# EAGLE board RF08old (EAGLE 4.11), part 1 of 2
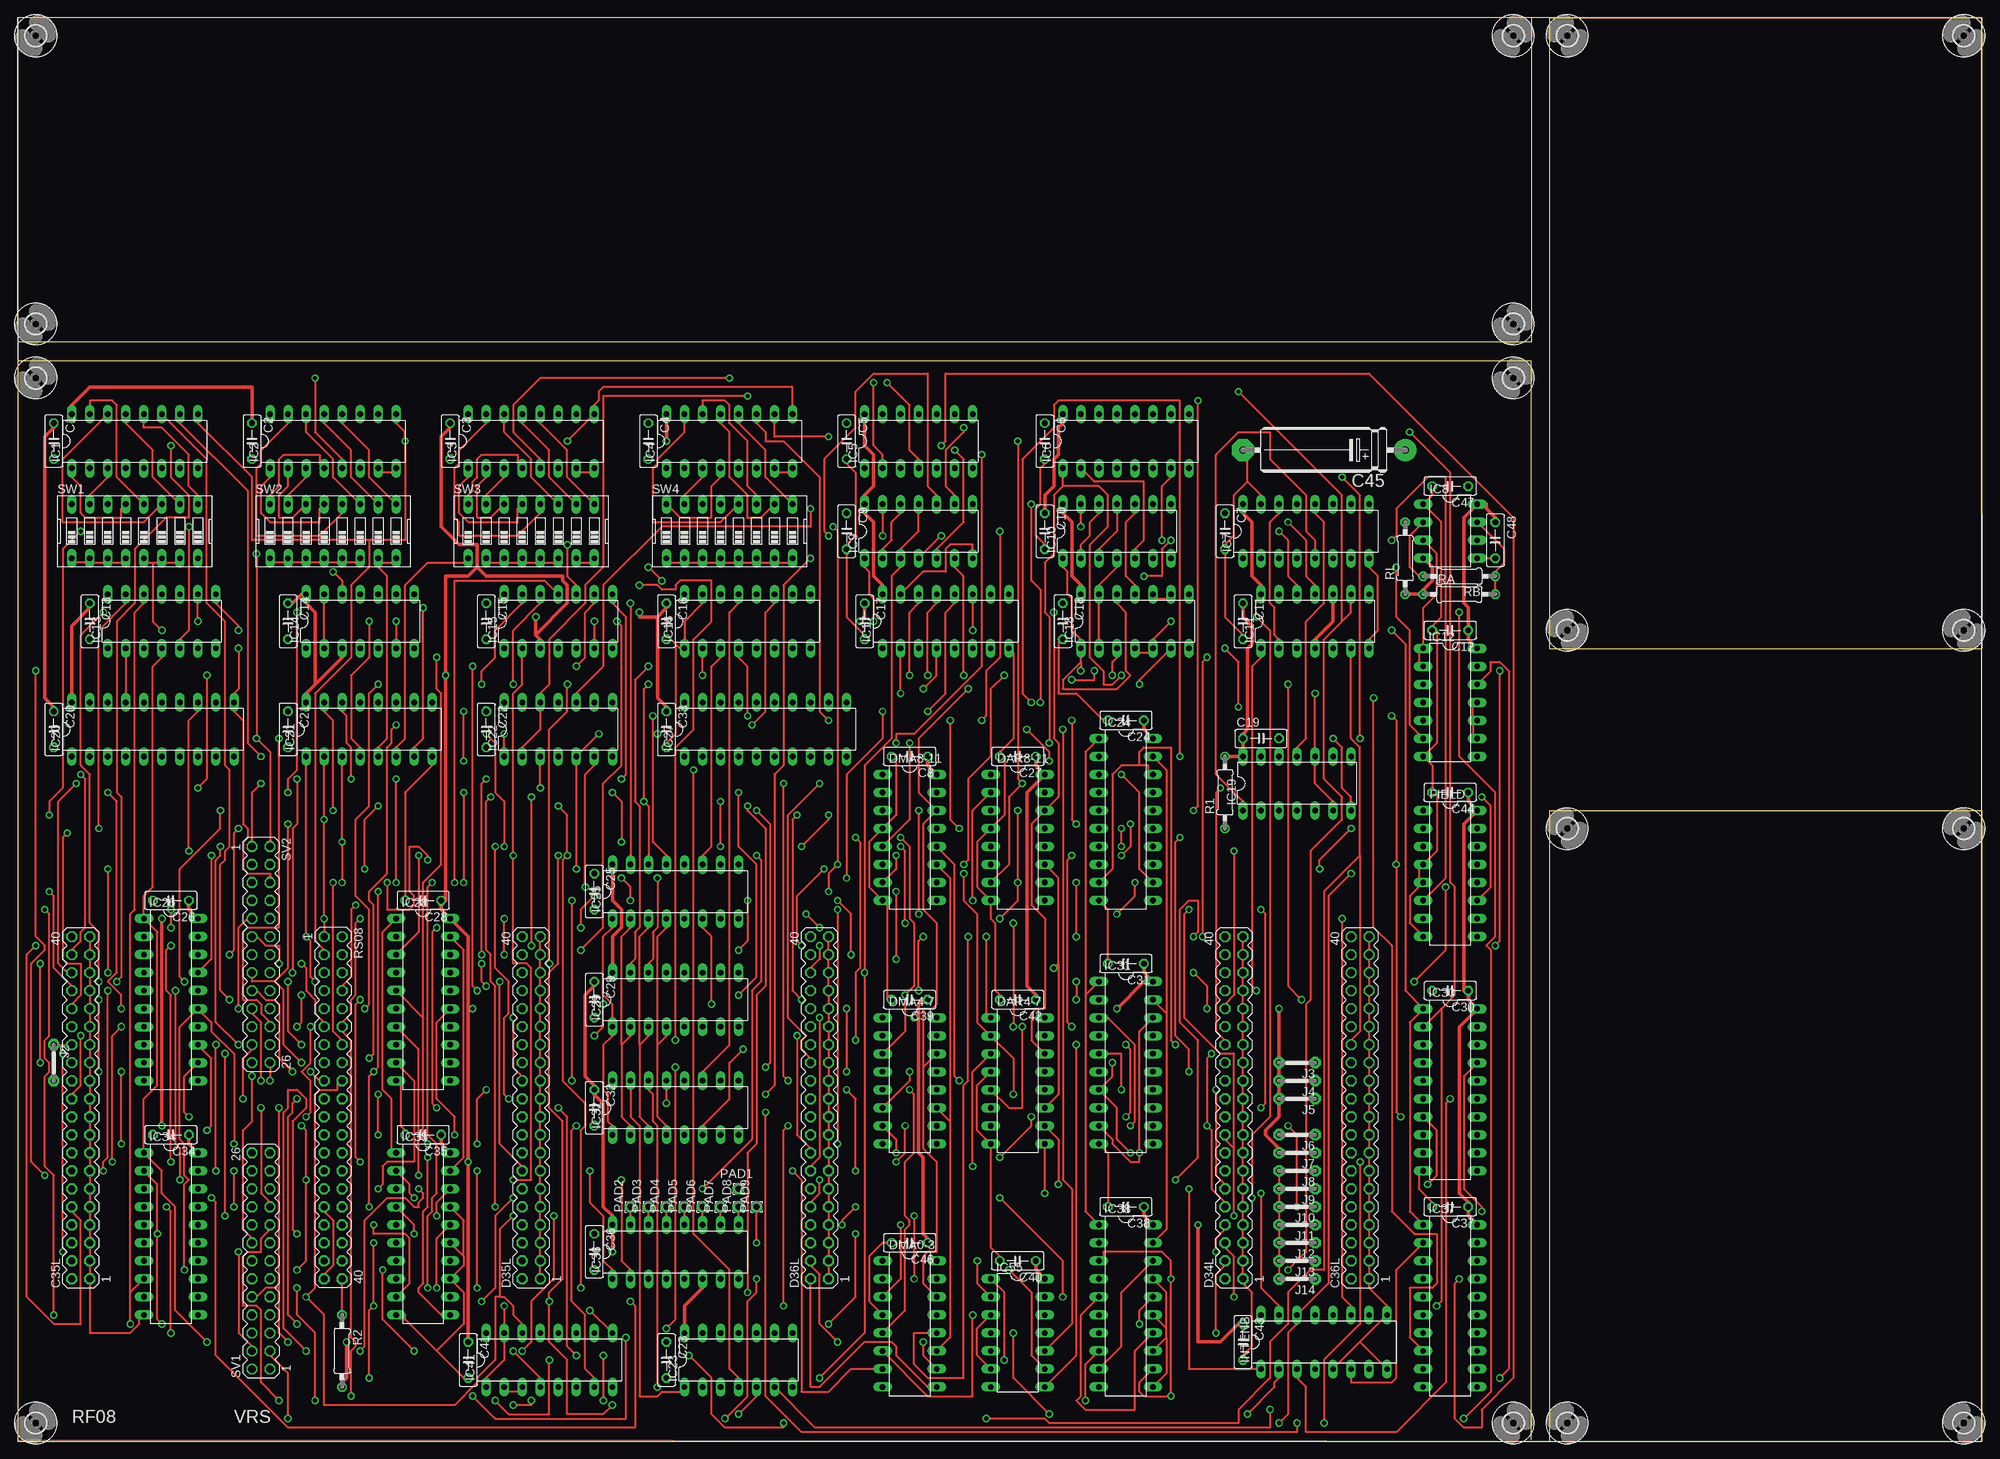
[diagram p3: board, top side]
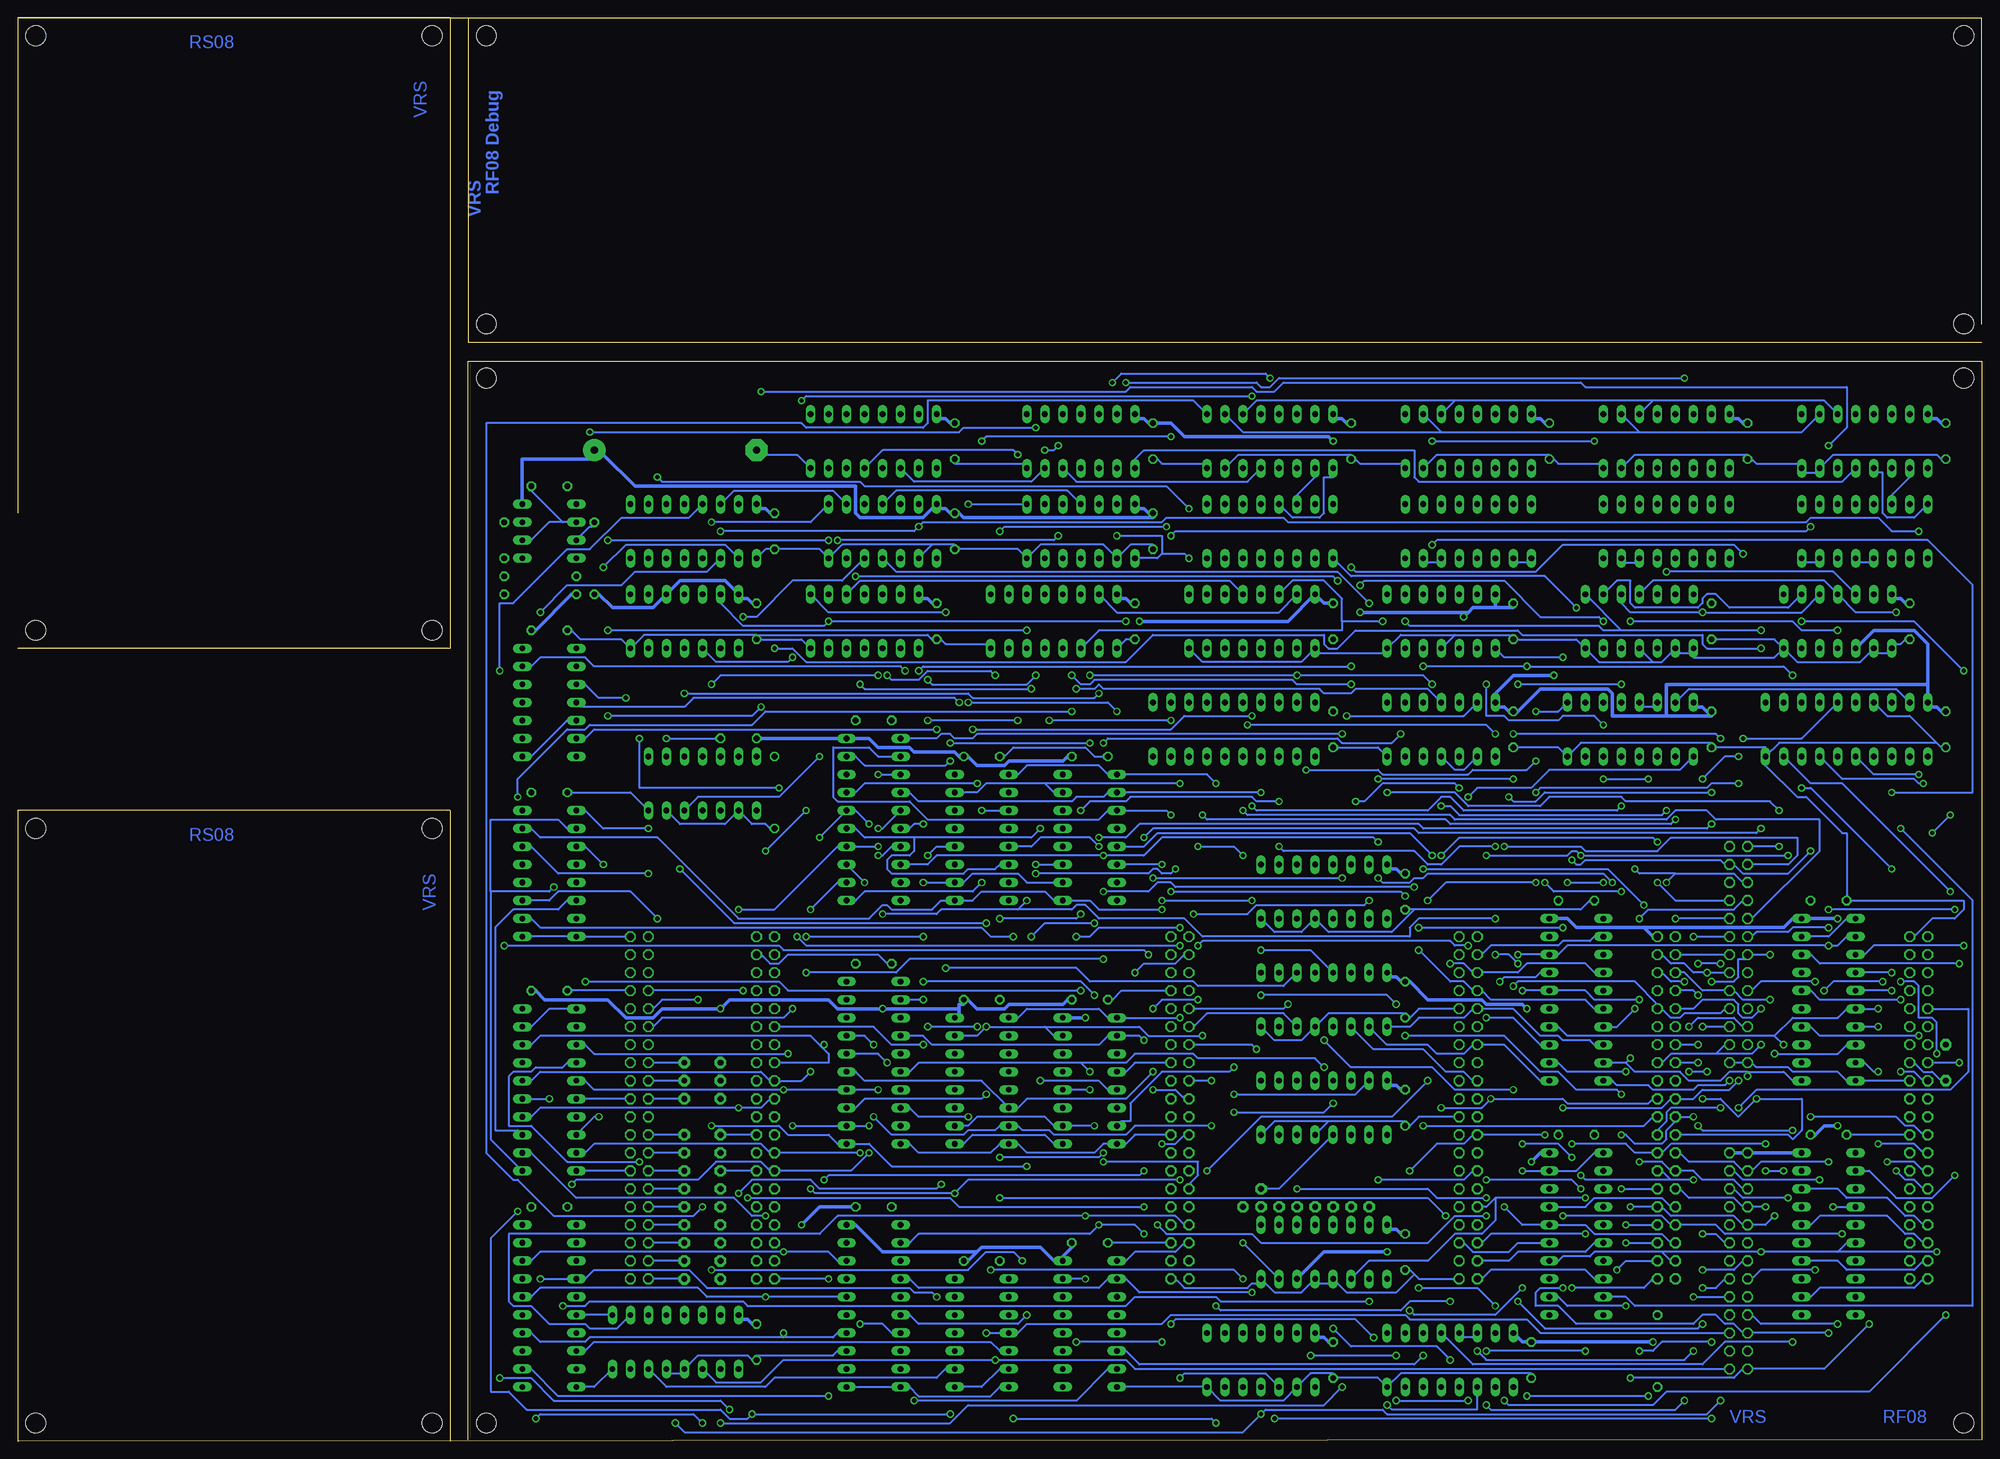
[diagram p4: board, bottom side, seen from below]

Size 276.86 x 200.67 mm. Coordinates in mm from the lower left corner, seen from the top.
Outline: 276.69,0 0.01,0.18 0.01,152.25 213.34,152.25 213.34,0.18
Outline: 215.9,0.01 215.9,88.92 276.86,88.92 276.86,0.01
Outline: 276.86,111.78 215.9,111.78 215.9,200.67 276.86,200.67
Outline: 276.86,200.67 0,200.67 0,157.49
Outline: 276.86,200.67 276.86,130.82
Outline: 0,154.95 213.36,154.95 213.36,200.67
Copper layers (1*16): Top 0.035mm / dielectric 1.5mm / Bottom 0.035mm
Design rules "olimex10mil": minimum track width 10mil, minimum drill 24mil, track to track 10mil, track to pad 10mil, pad to pad 10mil, via to via 10mil, smd to smd 10mil, copper to edge 40mil, drill to drill 10mil, minimum pad ring 10mil, minimum via ring 8mil, stop-mask expansion 0mil, vias tented up to drill 0mil, thermal gap 10mil
Net classes: 1 Power: width 0.508 mm

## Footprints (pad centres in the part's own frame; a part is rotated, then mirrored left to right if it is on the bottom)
C050-025X075 = drill 0.813 octagon: 1 -2.54,0; 2 2.54,0
MA20-2 = drill 1.016 octagon: 1 -24.13,-1.27; 2 -24.13,1.27; 3 -21.59,-1.27; 4 -21.59,1.27; 5 -19.05,-1.27; 6 -19.05,1.27; 7 -16.51,-1.27; 8 -16.51,1.27; 9 -13.97,-1.27; 10 -13.97,1.27; 11 -11.43,-1.27; 12 -11.43,1.27; 13 -8.89,-1.27; 14 -8.89,1.27; 15 -6.35,-1.27; 16 -6.35,1.27; 17 -3.81,-1.27; 18 -3.81,1.27; 19 -1.27,-1.27; 20 -1.27,1.27; 21 1.27,-1.27; 22 1.27,1.27; 23 3.81,-1.27; 24 3.81,1.27; 25 6.35,-1.27; 26 6.35,1.27; 27 8.89,-1.27; 28 8.89,1.27; 29 11.43,-1.27; 30 11.43,1.27; 31 13.97,-1.27; 32 13.97,1.27; 33 16.51,-1.27; 34 16.51,1.27; 35 19.05,-1.27; 36 19.05,1.27; 37 21.59,-1.27; 38 21.59,1.27; 39 24.13,-1.27; 40 24.13,1.27
E22-6 = drill 1.016 pad 3.15 round: + -11.43,0 | drill 1.016 pad 3.15 octagon: - 11.43,0
DIL16 = drill 0.813 long: 1 -8.89,-3.81; 2 -6.35,-3.81; 3 -3.81,-3.81; 4 -1.27,-3.81; 5 1.27,-3.81; 6 3.81,-3.81; 7 6.35,-3.81; 8 8.89,-3.81; 9 8.89,3.81; 10 6.35,3.81; 11 3.81,3.81; 12 1.27,3.81; 13 -1.27,3.81; 14 -3.81,3.81; 15 -6.35,3.81; 16 -8.89,3.81
DIL14 = drill 0.813 long: 1 -7.62,-3.81; 2 -5.08,-3.81; 3 -2.54,-3.81; 4 0,-3.81; 5 2.54,-3.81; 6 5.08,-3.81; 7 7.62,-3.81; 8 7.62,3.81; 9 5.08,3.81; 10 2.54,3.81; 11 0,3.81; 12 -2.54,3.81; 13 -5.08,3.81; 14 -7.62,3.81
DIL08 = drill 0.813 long: 1 -3.81,-3.81; 2 -1.27,-3.81; 3 1.27,-3.81; 4 3.81,-3.81; 5 3.81,3.81; 6 1.27,3.81; 7 -1.27,3.81; 8 -3.81,3.81
DIL20 = drill 0.813 long: 1 -11.43,-3.81; 2 -8.89,-3.81; 3 -6.35,-3.81; 4 -3.81,-3.81; 5 -1.27,-3.81; 6 1.27,-3.81; 7 3.81,-3.81; 8 6.35,-3.81; 9 8.89,-3.81; 10 11.43,-3.81; 11 11.43,3.81; 12 8.89,3.81; 13 6.35,3.81; 14 3.81,3.81; 15 1.27,3.81; 16 -1.27,3.81; 17 -3.81,3.81; 18 -6.35,3.81; 19 -8.89,3.81; 20 -11.43,3.81
05 = drill 0.813 pad 1.6 octagon: 1 -2.54,0; 2 2.54,0
1,6/0,8 = drill 0.813 pad 1.6 octagon: 1 0,0
0207/10 = drill 0.813 octagon: 1 -5.08,0; 2 5.08,0
MA13-2 = drill 1.016 octagon: 1 -15.24,-1.27; 2 -15.24,1.27; 3 -12.7,-1.27; 4 -12.7,1.27; 5 -10.16,-1.27; 6 -10.16,1.27; 7 -7.62,-1.27; 8 -7.62,1.27; 9 -5.08,-1.27; 10 -5.08,1.27; 11 -2.54,-1.27; 12 -2.54,1.27; 13 0,-1.27; 14 0,1.27; 15 2.54,-1.27; 16 2.54,1.27; 17 5.08,-1.27; 18 5.08,1.27; 19 7.62,-1.27; 20 7.62,1.27; 21 10.16,-1.27; 22 10.16,1.27; 23 12.7,-1.27; 24 12.7,1.27; 25 15.24,-1.27; 26 15.24,1.27
EDG-08 = drill 0.813 long: 1 -8.89,-3.81; 2 -6.35,-3.81; 3 -3.81,-3.81; 4 -1.27,-3.81; 5 1.27,-3.81; 6 3.81,-3.81; 7 6.35,-3.81; 8 8.89,-3.81; 9 8.89,3.81; 10 6.35,3.81; 11 3.81,3.81; 12 1.27,3.81; 13 -1.27,3.81; 14 -3.81,3.81; 15 -6.35,3.81; 16 -8.89,3.81
2,8 = hole 2.8: 0,0

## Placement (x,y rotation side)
C1  0.1  [C050-025X075]  5.08,140.98 270 top
C2  0.1  [C050-025X075]  33.02,140.98 270 top
C3  0.1  [C050-025X075]  60.96,140.98 270 top
C4  0.1  [C050-025X075]  88.9,140.98 270 top
C5  0.1  [C050-025X075]  116.84,140.98 270 top
C6  0.1  [C050-025X075]  144.78,140.98 270 top
C7  0.1  [C050-025X075]  170.18,128.28 270 top
C8  0.1  [C050-025X075]  125.73,96.53 180 top
C9  0.1  [C050-025X075]  116.84,128.28 270 top
C10  0.1  [C050-025X075]  144.78,128.28 270 top
C11  0.1  [C050-025X075]  172.72,115.58 270 top
C12  0.1  [C050-025X075]  201.93,114.31 180 top
C13  0.1  [C050-025X075]  10.16,115.58 270 top
C14  0.1  [C050-025X075]  38.1,115.58 270 top
C15  0.1  [C050-025X075]  66.04,115.58 270 top
C16  0.1  [C050-025X075]  91.44,115.58 270 top
C17  0.1  [C050-025X075]  119.38,115.58 270 top
C18  0.1  [C050-025X075]  147.32,115.58 270 top
C19  0.1  [C050-025X075]  175.26,99.08 0 top
C20  0.1  [C050-025X075]  5.08,100.34 270 top
C21  0.1  [C050-025X075]  38.1,100.34 270 top
C22  0.1  [C050-025X075]  66.04,100.34 270 top
C23  0.1  [C050-025X075]  91.44,11.45 270 top
C24  0.1  [C050-025X075]  156.21,101.61 180 top
C25  0.1  [C050-025X075]  81.28,77.48 270 top
C26  0.1  [C050-025X075]  21.59,76.22 180 top
C27  0.1  [C050-025X075]  140.97,96.53 180 top
C28  0.1  [C050-025X075]  57.15,76.22 180 top
C29  0.1  [C050-025X075]  81.28,62.24 270 top
C30  0.1  [C050-025X075]  201.93,63.52 180 top
C31  0.1  [C050-025X075]  156.21,67.33 180 top
C32  0.1  [C050-025X075]  81.28,47.01 270 top
C33  0.1  [C050-025X075]  91.44,100.34 270 top
C34  0.1  [C050-025X075]  21.59,43.2 180 top
C35  0.1  [C050-025X075]  57.15,43.2 180 top
C35L  [MA20-2]  8.89,47.01 90 top
C36  0.1  [C050-025X075]  81.28,26.69 270 top
C36L  [MA20-2]  189.23,47.01 90 top
C37  0.1  [C050-025X075]  201.93,33.04 180 top
C38  0.1  [C050-025X075]  156.21,33.04 180 top
C39  0.1  [C050-025X075]  125.73,62.24 180 top
C40  0.1  [C050-025X075]  140.97,25.41 180 top
C41  0.1  [C050-025X075]  63.5,11.45 270 top
C42  0.1  [C050-025X075]  140.97,62.24 180 top
C43  0.1  [C050-025X075]  172.72,13.99 270 top
C44  0.1  [C050-025X075]  201.93,91.45 180 top
C45  100uf  [E22-6]  184.15,139.71 180 top
C46  0.1  [C050-025X075]  125.73,27.96 180 top
C47  0.1  [C050-025X075]  201.93,134.63 180 top
C48  0.1  [C050-025X075]  208.28,127.02 270 top
D34L  [MA20-2]  171.45,47.01 90 top
D35L  [MA20-2]  72.39,47.01 90 top
D36L  [MA20-2]  113.03,47.01 90 top
DAR4-7  74LS193N  [DIL16]  140.97,50.81 270 top
DAR8-11  74LS193N  [DIL16]  140.97,85.11 270 top
DMA0-3  74LS193N  [DIL16]  125.73,16.53 270 top
DMA4-7  74LS193N  [DIL16]  125.73,50.81 270 top
DMA8-11  74LS193N  [DIL16]  125.73,85.11 270 top
FIELD  74LS193N  [DIL16]  201.93,80.03 270 top
IC1  74LS151N  [DIL16]  16.51,140.98 0 top
IC2  74LS151N  [DIL16]  44.45,140.98 0 top
IC3  74LS151N  [DIL16]  72.39,140.98 0 top
IC4  74LS151N  [DIL16]  100.33,140.98 0 top
IC5  74LS20N  [DIL14]  127,140.98 0 top
IC6  74LS139N  [DIL16]  156.21,140.98 0 top
IC7  74LS139N  [DIL16]  181.61,128.28 0 top
IC8  LM555N  [DIL08]  201.93,128.28 270 top
IC9  74S74N  [DIL14]  127,128.28 0 top
IC10  74S74N  [DIL14]  154.94,128.28 0 top
IC11  74S74N  [DIL14]  182.88,115.58 0 top
IC12  74LS00N  [DIL14]  201.93,104.16 270 top
IC13  74180N  [DIL14]  20.32,115.58 0 top
IC14  74180N  [DIL14]  48.26,115.58 0 top
IC15  74180N  [DIL14]  76.2,115.58 0 top
IC16  74LS139N  [DIL16]  102.87,115.58 0 top
IC17  74LS139N  [DIL16]  130.81,115.58 0 top
IC18  74LS00N  [DIL14]  157.48,115.58 0 top
IC19  7407N  [DIL14]  180.34,92.72 0 top
IC20  74S240N  [DIL20]  19.05,100.34 0 top
IC21  74LS139N  [DIL16]  49.53,100.34 0 top
IC22  7407N  [DIL14]  76.2,100.34 0 top
IC23  74S74N  [DIL14]  101.6,11.45 0 top
IC24  74S240N  [DIL20]  156.21,87.64 270 top
IC25  74S138N  [DIL16]  92.71,77.48 0 top
IC26  74S240N  [DIL20]  21.59,62.24 270 top
IC27  SPARE  [DIL20]  105.41,100.34 0 top
IC28  74LS244N  [DIL20]  57.15,62.24 270 top
IC29  74S138N  [DIL16]  92.71,62.24 0 top
IC30  74S240N  [DIL20]  201.93,49.55 270 top
IC31  74S240N  [DIL20]  156.21,53.36 270 top
IC32  74S138N  [DIL16]  92.71,47.01 0 top
IC34  74S240N  [DIL20]  21.59,29.23 270 top
IC35  74LS244N  [DIL20]  57.15,29.23 270 top
IC36  74S138N  [DIL16]  92.71,26.69 0 top
IC37  74S240N  [DIL20]  201.93,19.07 270 top
IC38  74S240N  [DIL20]  156.21,19.07 270 top
IC41  74LS139N  [DIL16]  74.93,11.45 0 top
IC55  7438N  [DIL14]  140.97,15.26 270 top
INTENB  74LS193N  [DIL16]  184.15,13.99 0 top
J2  J5MM  [05]  5.08,53.36 270 top
J3  J5MM  [05]  180.34,53.36 180 top
J4  J5MM  [05]  180.34,50.81 180 top
J5  J5MM  [05]  180.34,48.27 180 top
J6  J5MM  [05]  180.34,43.2 180 top
J7  J5MM  [05]  180.34,40.66 180 top
J8  J5MM  [05]  180.34,38.12 180 top
J9  J5MM  [05]  180.34,35.58 180 top
J10  J5MM  [05]  180.34,33.04 180 top
J11  J5MM  [05]  180.34,30.5 180 top
J12  J5MM  [05]  180.34,27.96 180 top
J13  J5MM  [05]  180.34,25.41 180 top
J14  J5MM  [05]  180.34,22.88 180 top
PAD1  [1,6/0,8]  101.6,35.58 90 top
PAD2  [1,6/0,8]  86.36,33.04 90 top
PAD3  [1,6/0,8]  88.9,33.04 90 top
PAD4  [1,6/0,8]  91.44,33.04 90 top
PAD5  [1,6/0,8]  93.98,33.04 90 top
PAD6  [1,6/0,8]  96.52,33.04 90 top
PAD7  [1,6/0,8]  99.06,33.04 90 top
PAD8  [1,6/0,8]  101.6,33.04 90 top
PAD9  [1,6/0,8]  104.14,33.04 90 top
R1  4.7K  [0207/10]  170.18,91.45 90 top
R2  4.7K  [0207/10]  45.72,12.71 270 top
RA  470K  [0207/10]  203.2,119.39 0 top
RB  1.5K  [0207/10]  203.2,121.94 180 top
RL  1K  [0207/10]  195.58,124.47 90 top
RS08  [MA20-2]  44.45,47.01 270 top
SV1  [MA13-2]  34.29,25.41 90 top
SV2  [MA13-2]  34.29,68.59 270 top
SW1  [EDG-08]  16.51,128.28 0 top
SW2  [EDG-08]  44.45,128.28 0 top
SW3  [EDG-08]  72.39,128.28 0 top
SW4  [EDG-08]  100.33,128.28 0 top
U$1  [2,8]  2.54,149.88 0 top
U$2  [2,8]  210.82,149.88 0 top
U$3  [2,8]  2.54,2.56 0 top
U$4  [2,8]  210.82,2.56 0 top
U$5  [2,8]  274.32,2.56 90 top
U$6  [2,8]  218.44,2.56 90 top
U$7  [2,8]  218.44,86.38 90 top
U$8  [2,8]  274.32,86.38 90 top
U$9  [2,8]  274.32,198.13 90 top
U$10  [2,8]  274.32,114.31 90 top
U$11  [2,8]  218.44,114.31 90 top
U$12  [2,8]  218.44,198.13 90 top
U$13  [2,8]  2.54,157.49 0 top
U$14  [2,8]  2.54,198.13 0 top
U$16  [2,8]  210.82,157.49 0 top
U$17  [2,8]  210.82,198.13 0 top
U$18  [SIERRA-PROTO]  0,0.01 0 top

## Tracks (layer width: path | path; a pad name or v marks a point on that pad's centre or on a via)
3CYC\
  Top 0.254: J2.1 C35L.28
601\  (via drill 0.61)
  Top 0.254: IC23.1 93.34,7 90.81,7 90.17,6.36 87.63,6.36 87.63,44.47 86.36,45.73 IC32.15 | IC9.13 v121.92,127.65 | IC18.4 158.12,111.14 159.38,111.14 IC18.5 160.02,113.05 v162.56,115.58 | v120.65,115.58 120.65,118.76 120.02,119.39 120.02,122.57 119.38,123.2 IC9.1 | v105.41,48.91 106.68,50.18 106.68,94 107.95,95.27 107.95,120.67 v111.76,124.47
  Bottom 0.254: 115.57,125.11 116.2,124.47 IC9.1 | 115.57,125.11 115.57,127.65 v121.92,127.65 | IC11.13 177.8,118.12 174.62,114.95 163.19,114.95 v162.56,115.58 v120.65,115.58 | v105.41,48.91 88.27,48.91 IC32.15 | v111.76,124.47 112.39,125.11 115.57,125.11
602\  (via drill 0.61)
  Top 0.254: v88.9,109.23 87,107.33 87,90.19 87.63,89.55 87.63,72.41 87,71.77 87,67.96 86.36,67.33 IC29.15 | 149.86,109.87 v149.86,108.6 | 149.86,109.87 IC18.1 149.86,113.05 148.59,114.31 148.59,118.76 147.96,119.39 147.96,122.57 147.32,123.2 IC10.1 | 149.86,109.87 147.32,107.33 147.32,106.06 154.94,106.06 156.84,107.97 156.21,108.6 156.21,116.86 154.94,118.12 IC18.12
  Bottom 0.254: v88.9,109.23 149.22,109.23 v149.86,108.6
604\  (via drill 0.61)
  Top 0.254: IC18.2 IC18.13 152.4,120.67 154.94,123.2 IC10.4 | v86.36,118.12 IC25.15
  Bottom 0.254: v86.36,118.12 90.81,122.57 153.03,122.57 IC10.4
611\  (via drill 0.61)
  Top 0.254: v90.17,7.63 90.17,44.47 89.53,45.1 89.53,48.91 88.9,49.55 IC32.14 | v177.8,2.56 179.07,3.83 179.07,15.26 180.34,16.53 INTENB.14 184.78,22.24 184.78,76.85 v187.96,80.03
  Bottom 0.254: v90.17,7.63 92.71,5.09 142.88,5.09 145.41,2.56 v177.8,2.56 | v187.96,80.03 200.66,80.03 204.47,83.83 FIELD.14
612\  (via drill 0.61)
  Top 0.254: v90.17,79.39 90.17,72.41 89.53,71.77 89.53,67.96 88.9,67.33 IC29.14 | v116.84,79.39 116.84,94 121.92,99.08 v121.92,102.89 | v142.88,104.16 141.6,105.42 141.6,138.44 146.05,142.89 146.05,146.06 146.69,146.7 163.83,146.7 v163.83,96.53
  Bottom 0.254: v116.84,79.39 v90.17,79.39 | v121.92,102.89 123.19,104.16 v142.88,104.16 | v163.83,96.53 169.54,90.82 180.97,90.82 IC19.5
614\  (via drill 0.61)
  Top 0.254: v73.66,92.09 IC22.3 | IC25.14 88.9,89.55 v88.27,90.19 88.27,106.06 v88.9,106.7 | v128.27,107.97 128.27,116.86 129.54,118.12 IC17.13
  Bottom 0.254: v73.66,92.09 74.3,92.72 84.45,92.72 87,90.19 v88.27,90.19 | v128.27,107.97 127,106.7 125.73,106.7 125.09,107.33 97.16,107.33 96.52,106.7 v88.9,106.7
621\  (via drill 0.61)
  Top 0.254: v105.41,46.37 105.41,6.36 110.49,1.28 180.34,1.28 v180.34,2.56 | v203.84,3.19 207.65,7 207.65,69.23 207.01,69.86 208.28,71.14 208.28,91.45 203.2,96.53 v203.2,116.86 | v91.44,47.64 IC32.13
  Bottom 0.254: v91.44,47.64 92.71,46.37 v105.41,46.37 | v180.34,2.56 181.61,3.83 203.2,3.83 v203.84,3.19 | v203.2,116.86 199.39,120.67 191.77,120.67 189.87,122.57 179.71,122.57 IC7.3
622\  (via drill 0.61)
  Top 0.254: v101.6,69.23 102.87,70.5 v102.87,76.22 | v115.57,76.22 117.47,74.31 v117.47,68.59 | v208.28,69.86 208.91,70.5 v208.91,108.6
  Bottom 0.254: v101.6,69.23 94.61,69.23 IC29.13 | v115.57,76.22 v102.87,76.22 | v117.47,68.59 118.11,69.23 168.91,69.23 169.54,69.86 v208.28,69.86 | v208.91,108.6 208.91,118.12 207.01,118.12 199.39,125.75 196.22,125.75 191.77,130.19 182.25,130.19 IC7.13
624\  (via drill 0.61)
  Top 0.254: 89.53,99.71 v89.53,102.25 | 89.53,99.71 89.53,84.47 91.44,82.56 IC25.13 | 150.5,62.88 150.5,32.4 IC38.1 | 150.5,62.88 IC31.1 | 150.5,62.88 150.5,97.17 IC24.1 | 89.53,99.71 v90.17,99.71
  Bottom 0.254: v89.53,102.25 73.03,102.25 IC22.13 | v90.17,99.71 141.6,99.71 142.24,99.08 144.78,99.08 145.41,99.71 146.69,99.71 147.32,99.08 IC24.1
641\
  Top 0.254: IC32.11 96.52,52.09 100.33,55.9 100.33,116.86 101.6,118.12 IC16.13
642\  (via drill 0.61)
  Top 0.254: v146.05,66.69 146.69,67.33 | 146.69,67.33 146.69,79.39 DAR8-11.11 | 146.69,67.33 146.69,48.91 DAR4-7.11
  Bottom 0.254: v146.05,66.69 127.64,66.69 125.73,64.78 111.12,64.78 110.49,64.15 98.42,64.15 IC29.11
644\
  Top 0.254: IC25.11 96.52,82.56 97.79,83.83 97.79,109.23 99.06,110.5 IC16.3
645\  (via drill 0.61)
  Top 0.254: 161.93,60.34 161.93,29.86 IC38.19 | 161.93,60.34 IC31.19 | 161.93,60.34 161.93,94.63 IC24.19 | v102.87,102.25 102.87,109.23 101.6,110.5 IC16.4 | v142.24,100.34 145.41,97.17 v145.41,95.9
  Bottom 0.254: v102.87,102.25 112.39,102.25 114.3,100.34 v142.24,100.34 | v145.41,95.9 146.05,95.27 157.48,95.27 158.75,96.53 IC24.19
ACB00\  (via drill 0.61)
  Top 0.254: IC38.12 158.12,8.27 158.12,7 158.75,6.36 v162.56,6.36 v162.56,22.88 162.56,25.41 161.29,26.69 153.03,26.69 153.03,26.05 IC38.3
  Bottom 0.254: v162.56,6.36 200.66,6.36 204.47,10.18 IC37.12 | v162.56,22.88 D34L.2
ACB01\  (via drill 0.61)
  Top 0.254: IC38.5 149.86,17.8 149.86,6.36 149.22,5.73 150.5,4.46 157.48,4.46 157.48,12.71 IC38.14 | v168.91,15.26 168.91,23.51 170.18,24.78 D34L.4
  Bottom 0.254: 168.91,14.62 196.22,14.62 196.85,13.99 203.2,13.99 204.47,15.26 IC37.14 | 168.91,14.62 161.93,14.62 161.29,15.26 IC38.14 | 168.91,14.62 v168.91,15.26
ACB02\  (via drill 0.61)
  Top 0.254: v158.12,16.53 158.12,18.43 IC38.16 | v171.45,20.34 171.45,26.05 170.18,27.32 D34L.6
  Bottom 0.254: v158.12,16.53 154.94,16.53 153.67,15.26 IC38.7 | IC37.16 204.47,20.34 203.2,21.61 180.97,21.61 179.71,20.34 v171.45,20.34 IC38.16
ACB03\  (via drill 0.61)
  Top 0.254: IC38.9 155.57,13.35 155.57,20.97 IC38.18 | v168.91,26.69 168.91,28.59 170.18,29.86 D34L.8
  Bottom 0.254: IC37.18 204.47,25.41 203.2,26.69 v168.91,26.69 162.56,26.69 161.29,25.41 IC38.18
ACB04\  (via drill 0.61)
  Top 0.254: D34L.10 170.18,33.67 168.28,35.58 168.28,43.83 v167.64,44.47 167.64,53.99 v168.28,54.62 | v156.84,44.47 157.48,45.1 157.48,55.9 153.67,59.7 IC31.3
  Bottom 0.254: v167.64,44.47 IC31.12 v156.84,44.47 | v168.28,54.62 195.58,54.62 196.85,55.9 IC30.3
ACB05\  (via drill 0.61)
  Top 0.254: v155.57,49.55 155.57,54.62 IC31.5 | v168.91,49.55 168.91,37.48 170.18,36.21 D34L.12
  Bottom 0.254: v155.57,49.55 IC31.14 v168.91,49.55 195.58,49.55 196.85,50.81 IC30.5
ACB06\  (via drill 0.61)
  Top 0.254: v154.31,53.36 154.31,51.45 IC31.7 154.94,47.01 154.94,42.56 v156.84,40.66 | v198.75,36.21 200.03,37.48 200.03,43.83 IC30.7
  Bottom 0.254: v154.31,53.36 155.57,54.62 IC31.16 | v198.75,36.21 198.12,36.84 180.97,36.84 178.44,39.38 172.09,39.38 170.81,38.12 D34L.14 159.38,38.12 v156.84,40.66
ACB07\  (via drill 0.61)
  Top 0.254: IC31.9 154.31,42.56 154.31,41.92 156.84,39.38 158.12,39.38 v158.12,40.66 158.12,57.8 IC31.18
  Bottom 0.254: IC30.9 196.85,40.66 195.58,41.92 172.09,41.92 170.81,40.66 D34L.16 v158.12,40.66
ACB08\  (via drill 0.61)
  Top 0.254: v155.57,94 158.12,91.45 158.12,80.66 IC24.12 | v171.45,31.77 171.45,41.29 | 171.45,41.29 170.18,42.56 D34L.18 | v165.1,74.95 164.47,74.31 164.47,59.7 169.54,54.62 171.45,54.62 171.45,41.29
  Bottom 0.254: v155.57,94 IC24.3 | v171.45,31.77 173.35,31.77 175.9,34.3 198.12,34.3 204.47,40.66 IC30.12 | v165.1,74.95 161.29,78.75 IC24.12
ACB09\  (via drill 0.61)
  Top 0.254: v155.57,83.83 v155.57,86.38 | v175.26,74.95 175.9,74.31 175.9,47.64 v175.26,47.01
  Bottom 0.254: v155.57,86.38 154.94,86.38 IC24.5 | v155.57,83.83 IC24.14 161.29,83.83 170.18,74.95 v175.26,74.95 | IC30.14 204.47,45.73 203.2,47.01 v175.26,47.01 172.09,47.01 170.81,48.27 D34L.22
ACB10\  (via drill 0.61)
  Top 0.254: v155.57,82.56 156.84,83.83 v156.84,87.01 | v163.83,85.11 163.19,84.47 163.19,57.16 165.1,55.26 v165.1,52.09
  Bottom 0.254: v155.57,82.56 154.94,82.56 153.67,83.83 IC24.7 | v156.84,87.01 158.75,88.92 IC24.16 v163.83,85.11 | IC30.16 204.47,50.81 203.2,52.09 172.09,52.09 170.81,50.81 D34L.24 166.37,50.81 v165.1,52.09
ACB11\  (via drill 0.61)
  Top 0.254: 158.12,95.27 159.38,95.27 159.38,94.63 IC24.18 | 158.12,95.27 155.57,95.27 154.31,94 154.31,80.66 IC24.9 | 158.12,95.27 158.12,97.17 158.75,97.81 162.56,97.81 162.56,56.53 v163.19,55.9
  Bottom 0.254: 163.83,55.9 162.56,54.62 162.56,53.36 D34L.26 | 163.83,55.9 165.1,57.16 203.2,57.16 204.47,55.9 IC30.18 | v163.19,55.9 163.83,55.9
ACCLEAR\  (via drill 0.61)
  Top 0.254: IC22.2 71.12,97.81 73.66,100.34 IC22.12 73.66,105.42 74.93,106.7 74.93,113.05 80.01,118.12 80.01,120.67 82.55,123.2 82.55,147.33 v102.87,147.33 | v171.45,83.2 171.45,62.88 170.18,61.61 D34L.32 | v165.74,88.92 166.37,89.55 v166.37,146.7
  Bottom 0.254: IC22.4 74.3,94.63 73.03,94.63 IC22.2 | v165.74,88.92 v171.45,83.2 | v166.37,146.7 165.74,147.33 v102.87,147.33
BAC00
  Top 0.254: DMA0-3.9 128.27,7.63 123.83,12.08 123.83,13.35 123.19,13.99 119.38,13.99 113.03,7.63 111.76,7.63 D36L.2
BAC01  (via drill 0.61)
  Top 0.254: v127.64,13.99 127.64,12.08 DMA0-3.10 | v115.57,13.99 113.03,16.53 113.03,23.51 111.76,24.78 D36L.4
  Bottom 0.254: v115.57,13.99 v127.64,13.99
BAC02
  Bottom 0.254: DMA0-3.1 120.65,25.41 119.38,26.69 113.67,26.69 112.39,27.96 D36L.6
BAC03  (via drill 0.61)
  Top 0.254: v126.36,31.77 v126.36,22.88
  Bottom 0.254: v126.36,22.88 DMA0-3.15 | D36L.8 112.39,30.5 113.67,31.77 v126.36,31.77 161.29,31.77 163.83,29.23 207.65,29.23 207.65,19.7 207.01,19.07 204.47,19.07 201.93,16.53 196.85,16.53 196.22,15.89 192.41,15.89 INTENB.10
BAC04  (via drill 0.61)
  Top 0.254: v165.1,35.58 165.1,10.18 INTENB.1 | v144.78,34.94 DAR4-7.9 | v113.03,36.84 113.03,34.94 111.76,33.67 D36L.10
  Bottom 0.254: DMA4-7.9 130.81,41.92 132.08,43.2 142.24,43.2 143.51,41.92 DAR4-7.9 | v165.1,35.58 164.47,34.94 v144.78,34.94 142.88,36.84 v113.03,36.84
BAC05  (via drill 0.61)
  Top 0.254: v175.26,34.94 175.26,21.61 177.8,19.07 INTENB.15 | v146.69,36.21 146.69,42.56 DAR4-7.10 | v123.83,39.38 125.09,40.66 v125.09,44.47
  Bottom 0.254: DAR4-7.10 142.88,44.47 141.6,45.73 132.08,45.73 130.81,44.47 DMA4-7.10 v125.09,44.47 | v175.26,34.94 173.35,36.84 165.1,36.84 163.83,35.58 147.32,35.58 v146.69,36.21 | v123.83,39.38 110.49,39.38 110.49,37.48 111.76,36.21 D36L.12
BAC06  (via drill 0.61)
  Top 0.254: v136.53,71.14 136.53,60.34 DAR4-7.1 | v113.03,59.7 113.03,40.02 111.76,38.75 D36L.14
  Bottom 0.254: DAR4-7.1 135.89,59.7 134.62,60.98 124.46,60.98 123.19,59.7 DMA4-7.1 v113.03,59.7 | v136.53,71.14 139.7,71.14 140.97,72.41 203.2,72.41 204.47,73.67 FIELD.10
BAC07  (via drill 0.61)
  Top 0.254: v187.96,86.38 183.51,81.93 v183.51,80.66 | v140.34,73.04 v140.34,58.44 | v109.86,57.16 109.86,43.2 111.76,41.29 D36L.16
  Bottom 0.254: 132.08,58.44 130.81,57.16 DMA4-7.15 | 132.08,58.44 v140.34,58.44 141.6,57.16 DAR4-7.15 | v187.96,86.38 194.31,86.38 196.85,88.92 FIELD.1 | v183.51,80.66 175.9,73.04 v140.34,73.04 | v109.86,57.16 117.47,57.16 118.75,58.44 132.08,58.44
BAC08  (via drill 0.61)
  Top 0.254: v115.57,74.95 v115.57,41.92
  Bottom 0.254: FIELD.15 204.47,86.38 203.2,85.11 186.69,85.11 175.26,73.67 156.84,73.67 154.94,75.58 154.31,75.58 153.67,74.95 147.96,74.95 146.69,76.22 DAR8-11.9 142.24,76.22 140.97,77.48 132.08,77.48 130.81,76.22 DMA8-11.9 125.73,76.22 124.46,74.95 v115.57,74.95 | v115.57,41.92 113.67,41.92 112.39,43.2 D36L.18
BAC09  (via drill 0.61)
  Top 0.254: v116.84,49.55 118.11,48.27 v118.11,38.12 | v163.19,36.84 166.37,40.02 166.37,56.53 163.83,59.07 163.83,74.95 165.1,76.22 166.37,76.22 166.37,71.77 v165.74,71.14 | v149.22,71.14 v149.22,78.75
  Bottom 0.254: DMA8-11.10 134.62,78.75 135.89,80.03 142.24,80.03 143.51,78.75 DAR8-11.10 v149.22,78.75 | v116.84,49.55 113.67,49.55 112.39,48.27 D36L.22 | v118.11,38.12 118.75,37.48 162.56,37.48 v163.19,36.84 | v165.74,71.14 v149.22,71.14
BAC10  (via drill 0.61)
  Top 0.254: v108.58,50.81 107.95,51.45 v107.95,92.72
  Bottom 0.254: DAR8-11.1 135.89,94 134.62,95.27 124.46,95.27 123.19,94 DMA8-11.1 109.22,94 v107.95,92.72 | v108.58,50.81 D36L.24
BAC11  (via drill 0.61)
  Top 0.254: v113.03,92.72 108.58,88.28 108.58,59.7 111.12,57.16 110.49,56.53 110.49,55.26 111.76,53.99 D36L.26
  Bottom 0.254: 132.08,92.72 130.81,91.45 DMA8-11.15 | 132.08,92.72 140.34,92.72 141.6,91.45 DAR8-11.15 | v113.03,92.72 132.08,92.72
BADDAC\  (via drill 0.61)
  Top 0.254: v174.62,63.52 173.99,64.15 173.99,109.23 175.26,110.5 IC11.1
  Bottom 0.254: v174.62,63.52 C36L.34
BBREAK\  (via drill 0.61)
  Top 0.254: IC41.1 66.04,8.91 68.58,11.45 IC41.15 v68.58,19.07 | v125.73,98.44 125.73,87.64 DMA8-11.5 | v145.41,98.44 145.41,116.22 144.78,116.86 144.78,123.84 146.05,125.11 146.05,133.36 147.32,134.63 | 147.32,134.63 IC6.1 | v180.97,62.24 179.07,64.15 v179.07,106.7 | v155.57,107.97 154.31,106.7 153.03,106.7 153.03,108.6 151.13,110.5 151.13,126.38 153.67,128.92 153.67,133.36 152.4,134.63 147.32,134.63 | v79.38,21.61 79.38,43.83 80.01,44.47 80.01,47.64 76.83,50.81 76.83,81.93 v77.47,82.56 77.47,88.28 v76.2,89.55 | v44.45,88.92 44.45,101.61 43.18,102.89 IC21.15
  Bottom 0.254: IC20.19 12.06,106.06 41.27,106.06 IC21.15 | v145.41,98.44 v125.73,98.44 | v180.97,62.24 186.06,62.24 187.32,60.98 C36L.32 | v179.07,106.7 177.8,107.97 v155.57,107.97 | v68.58,19.07 71.12,21.61 v79.38,21.61 | v77.47,82.56 80.64,85.74 116.2,85.74 118.11,83.83 DMA8-11.5 | v44.45,88.92 45.09,88.28 73.66,88.28 74.93,89.55 v76.2,89.55
BINIT  (via drill 0.61)
  Top 0.254: IC9.11 127,128.28 124.46,125.75 IC9.3 124.46,123.2 123.19,121.94 123.19,99.08 119.38,95.27 v119.38,66.06 119.38,15.26 v113.03,8.91 | IC10.3 152.4,125.75 154.94,128.28 IC10.11
  Bottom 0.254: IC9.11 128.91,134 153.03,134 IC10.11 | v113.03,8.91 112.39,9.54 100.97,9.54 IC23.3 | v119.38,66.06 118.11,67.33 113.67,67.33 112.39,68.59 D36L.38
BIOP1  (via drill 0.61)
  Top 0.254: v102.23,55.26 100.33,53.36 100.33,48.27 96.52,44.47 IC32.6
  Bottom 0.254: v102.23,55.26 102.87,55.9 D36L.28
BIOP2
  Bottom 0.254: IC29.6 98.42,60.34 109.22,60.34 111.12,58.44 D36L.30
BIOP4  (via drill 0.61)
  Top 0.254: v97.79,61.61 97.79,71.14 96.52,72.41 IC25.6
  Bottom 0.254: v97.79,61.61 98.42,60.98 D36L.32
BMB00
  Bottom 0.254: IC35.8 54.61,22.88 55.88,24.14 69.22,24.14 70.48,22.88 D35L.2
BMB01
  Bottom 0.254: IC35.6 54.61,27.96 55.88,26.69 65.41,26.69 66.67,25.41 D35L.4
BMB02  (via drill 0.61)
  Top 0.254: v55.88,29.23 55.88,30.5 IC35.4
  Bottom 0.254: v55.88,29.23 69.22,29.23 70.48,27.96 D35L.6
BMB03  (via drill 0.61)
  Top 0.254: v55.88,34.3 55.24,34.94 55.24,36.21 IC35.2
  Bottom 0.254: v55.88,34.3 68.58,34.3 | 68.58,34.3 69.85,33.04 D35L.10 | 68.58,34.3 68.58,31.13 70.48,29.23 74.3,29.23 78.11,25.41 86.36,25.41 IC36.3
BMB04  (via drill 0.61)
  Top 0.254: v85.09,36.84 85.09,25.41 86.36,24.14 IC36.2 | v67.94,64.78 67.94,41.92 71.12,38.75 D35L.14
  Bottom 0.254: v85.09,36.84 73.03,36.84 71.75,38.12 D35L.14 | v67.94,64.78 67.31,65.42 62.87,65.42 62.23,66.06 IC28.17
BMB05  (via drill 0.61)
  Top 0.254: v80.64,38.12 80.64,33.67 82.55,31.77 82.55,25.41 83.82,24.14 IC36.1 | v61.59,43.2 61.59,45.73 59.05,48.27 59.05,59.07 IC28.15
  Bottom 0.254: v80.64,38.12 76.83,41.92 73.03,41.92 71.75,43.2 D35L.18 v61.59,43.2
BMB06  (via drill 0.61)
  Top 0.254: v69.85,59.7 69.85,52.72 71.12,51.45 D35L.24 | 87.63,55.9 87.63,45.73 88.9,44.47 IC32.3 | 87.63,55.9 88.9,57.16 IC29.3 | 87.63,55.9 87.63,71.14 88.9,72.41 IC25.3
  Bottom 0.254: v69.85,59.7 66.04,59.7 62.23,55.9 IC28.13 | D35L.24 71.75,50.81 73.03,52.09 75.56,52.09 78.74,55.26 85.72,55.26 IC29.3
BMB07
  Top 0.254: 85.09,55.9 85.09,45.73 86.36,44.47 IC32.2 | 85.09,55.9 86.36,57.16 IC29.2 | 85.09,55.9 85.09,71.14 86.36,72.41 IC25.2
  Bottom 0.254: IC28.11 62.23,50.81 67.31,55.9 D35L.28 71.75,55.9 73.03,54.62 76.83,54.62 78.11,55.9 83.82,55.9 IC29.2
BMB08
  Top 0.254: IC32.1 83.82,44.47 83.19,45.1 83.19,48.91 82.55,49.55 82.55,55.9 83.82,57.16 IC29.1 83.82,61.61 82.55,62.88 82.55,71.14 83.82,72.41 IC25.1
  Bottom 0.254: IC28.8 54.61,55.9 55.24,56.53 59.05,56.53 59.69,57.16 62.23,57.16 66.04,60.98 D35L.32 71.75,60.98 73.03,59.7 79.38,59.7 80.64,58.44 IC29.1
BMB09  (via drill 0.61)
  Top 0.254: v79.38,69.23 82.55,72.41 82.55,92.72 85.09,95.27 85.09,114.95 v84.45,115.58
  Bottom 0.254: IC28.6 54.61,60.98 55.88,62.24 69.22,62.24 70.48,63.52 D35L.34 71.75,63.52 73.03,64.78 74.93,64.78 v79.38,69.23 | 90.17,115.58 90.17,114.31 124.46,114.31 IC17.3 | 90.17,115.58 90.17,118.76 92.71,121.3 97.16,121.3 IC16.14 | v84.45,115.58 90.17,115.58
BMB10  (via drill 0.61)
  Top 0.254: v125.73,107.97 125.73,116.86 127,118.12 IC17.14 | v96.52,107.97 IC16.2 | v74.93,67.33 74.93,100.34 77.47,102.89 v77.47,106.7
  Bottom 0.254: IC28.4 54.61,66.06 55.88,67.33 64.14,67.33 65.41,66.06 D35L.36 71.75,66.06 73.03,67.33 v74.93,67.33 | v125.73,107.97 v96.52,107.97 78.74,107.97 v77.47,106.7
BMB11
  Bottom 0.254: IC28.2 54.61,71.14 55.24,70.5 59.05,70.5 59.69,69.86 69.22,69.86 70.48,68.59 D35L.38
BRK_RQ\  (via drill 0.61)
  Top 0.254: 189.23,82.56 189.23,57.8 187.96,56.53 C36L.28 | 189.23,82.56 189.23,97.81 187.96,99.08 IC11.6 | v39.37,21.61 39.37,17.8 41.91,15.26 v41.91,5.73 | v69.85,5.09 72.39,5.09 v72.39,5.73 | v82.55,12.08 v82.55,5.73 | v94.61,12.08 97.79,8.91 97.79,3.83 99.69,1.92 107.95,1.92 v107.95,2.56 | v136.53,3.19 144.78,3.19 145.41,2.56 172.09,2.56 172.09,4.46 176.53,8.91 176.53,13.99 179.07,16.53 179.07,20.97 182.25,24.14 184.15,24.14 184.15,77.48 189.23,82.56
  Bottom 0.254: v39.37,21.61 37.47,21.61 36.2,22.88 SV1.11 | v41.91,5.73 43.18,4.46 69.22,4.46 v69.85,5.09 | v82.55,5.73 v72.39,5.73 | v94.61,12.08 v82.55,12.08 | v107.95,2.56 108.58,3.19 v136.53,3.19
BTS1  (via drill 0.61)
  Top 0.254: v167.64,110.5 167,109.87 v167,71.14 | v113.03,69.86 113.03,67.96 111.76,66.69 D36L.36
  Bottom 0.254: v167.64,110.5 168.28,109.87 178.44,109.87 IC11.3 | v167,71.14 165.74,69.86 v113.03,69.86
BUSY
  Top 0.254: IC11.2 177.8,113.05 177.16,113.68 177.16,117.49 176.53,118.12 176.53,129.55 177.8,130.82 IC7.14
  Bottom 0.254: IC10.9 161.93,134 175.9,134 IC7.14
BWC0\  (via drill 0.61)
  Top 0.254: v177.8,128.28 179.07,127.02 179.07,121.94 180.34,120.67 IC11.12 | v149.86,128.92 IC10.13 | v34.29,47.01 34.29,34.94 35.56,33.67 SV1.19 | v8.89,128.28 6.35,125.75 6.35,92.09 4.45,90.19 v4.45,88.28 | v6.99,85.74 6.35,85.11 6.35,67.96 6.99,67.33 8.89,67.33 8.89,62.88 7.62,61.61 C35L.32
  Bottom 0.254: v177.8,128.28 150.5,128.28 v149.86,128.92 149.22,129.55 115.57,129.55 114.94,130.19 98.42,130.19 97.79,129.55 24.77,129.55 24.13,130.19 14.61,130.19 12.7,128.28 v8.89,128.28 | v34.29,47.01 31.75,49.55 4.45,49.55 1.91,52.09 1.91,60.98 C35L.32 | v4.45,88.28 v6.99,85.74
CIE  (via drill 0.61)
  Top 0.254: v139.06,11.45 139.06,20.97 IC55.1 | v201.93,48.27 201.29,47.64 201.29,8.27 194.31,1.28 181.61,1.28 181.61,7.63 180.34,8.91 INTENB.3
  Bottom 0.254: INTENB.3 178.44,8.27 172.09,8.27 168.91,11.45 v139.06,11.45 120.65,11.45 119.38,10.18 SV1.1 | IC30.15 v201.93,48.27
DA00\
  Bottom 0.254: J14.1 C36L.2
DA01\
  Bottom 0.254: J13.1 C36L.4
DA02\
  Bottom 0.254: J12.1 C36L.6
DA03\
  Bottom 0.254: J11.1 C36L.8
DA04\
  Bottom 0.254: J10.1 C36L.10
DA05\
  Bottom 0.254: J9.1 C36L.12
DA06\
  Bottom 0.254: J8.1 C36L.14
DA07\
  Bottom 0.254: J7.1 C36L.16
DA08\
  Bottom 0.254: J6.1 C36L.18
DA09\
  Bottom 0.254: J5.1 C36L.22
DA10\
  Bottom 0.254: J4.1 C36L.24
DA11\
  Bottom 0.254: J3.1 C36L.26
DAR04  (via drill 0.61)
  Top 0.254: v156.21,45.73 156.84,46.37 156.84,55.26 v156.21,55.9 | IC41.2 69.22,7 70.48,7 IC41.3 | v45.72,78.75 v45.72,84.47 IC21.3 | v83.82,5.09 82.55,3.83 77.47,3.83 77.47,11.45 74.93,13.99 v74.93,19.7 74.93,20.97 76.83,22.88 76.83,45.1 74.93,47.01 74.93,66.06 76.2,67.33 v76.2,82.56 | v108.58,44.47 107.95,43.83 v107.95,19.07
  Bottom 0.254: v156.21,45.73 153.67,43.2 143.51,43.2 142.88,43.83 139.06,43.83 138.43,44.47 DAR4-7.7 135.89,44.47 135.25,43.83 131.44,43.83 130.81,43.2 120.65,43.2 119.38,44.47 v108.58,44.47 | v156.21,55.9 157.48,57.16 IC31.17 | v45.72,78.75 43.18,76.22 SV2.8 | v83.82,5.09 83.19,4.46 71.12,4.46 IC41.3 | v76.2,82.56 73.66,85.11 46.35,85.11 v45.72,84.47 | v107.95,19.07 107.31,18.43 81.92,18.43 80.64,19.7 v74.93,19.7
DAR05  (via drill 0.61)
  Top 0.254: IC21.2 v43.18,87.64 v43.18,73.67 RS08.1 | v116.84,60.98 v116.84,52.09 | v110.49,62.24 109.22,63.52 109.22,87.64 v109.86,88.28
  Bottom 0.254: IC31.15 158.75,52.09 157.48,50.81 140.97,50.81 DAR4-7.6 135.89,47.01 134.62,48.27 120.65,48.27 v116.84,52.09 | SV2.10 v43.18,73.67 | v116.84,60.98 115.57,62.24 v110.49,62.24 | v109.86,88.28 109.22,87.64 75.56,87.64 74.93,87.01 43.81,87.01 v43.18,87.64
DAR06  (via drill 0.61)
  Top 0.254: v140.34,48.91 140.34,53.99 DAR4-7.2 135.25,59.07 135.25,74.31 133.35,76.22 v133.35,80.03 | IC21.1 v40.64,71.14 41.27,70.5 41.27,65.42 v41.91,64.78 | v113.67,80.66 109.86,76.85 109.86,70.5 v110.49,69.86 | v72.39,90.82 v72.39,69.86
  Bottom 0.254: v140.34,48.91 140.97,48.27 157.48,48.27 158.75,47.01 IC31.13 | v40.64,71.14 SV2.12 | v41.91,64.78 43.81,64.78 45.09,66.06 RS08.6 | v133.35,80.03 117.47,80.03 116.84,80.66 116.2,80.66 115.57,80.03 114.3,80.03 v113.67,80.66 | v110.49,69.86 109.86,70.5 74.93,70.5 74.3,69.86 v72.39,69.86 | v72.39,90.82 71.12,92.09 63.5,92.09 60.96,94.63 42.55,94.63 IC21.1
DAR07  (via drill 0.61)
  Top 0.254: v134.62,38.75 134.62,52.09 DAR4-7.3 | IC4.9 109.22,148.6 82.55,148.6 81.92,147.97 81.92,146.7 81.28,146.06 IC3.9 v77.47,140.98 | 49.53,127.02 54.61,127.02 v54.61,140.98 54.61,142.25 53.34,143.52 IC2.9 | 49.53,127.02 33.02,127.02 33.02,135.9 25.4,143.52 IC1.9 | 49.53,127.02 49.53,123.2 46.99,120.67 46.99,110.5 41.91,105.42 41.91,70.5 43.18,69.23 RS08.3 | v179.07,44.47 180.34,43.2 v180.34,33.04
  Bottom 0.254: v134.62,38.75 153.67,38.75 156.84,41.92 IC31.11 161.29,41.92 162.56,43.2 168.28,43.2 169.54,44.47 v179.07,44.47 | RS08.3 SV2.14 | v77.47,140.98 v54.61,140.98 | v180.34,33.04 181.61,31.77 201.29,31.77 206.38,36.84 207.01,36.84 210.82,40.66 210.82,143.52 166.37,143.52 165.74,142.89 149.22,142.89 148.59,143.52 148.59,146.7 111.12,146.7 IC4.9
DAR08  (via drill 0.61)
  Top 0.254: DAR8-11.7 139.7,81.3 139.7,90.82 v141.6,92.72 140.97,93.36 v140.97,140.98 | v38.73,66.06 38.73,86.38 39.37,87.01 v39.37,93.36 | v34.29,96.53 32.38,98.44 32.38,134 22.86,143.52 IC1.10 | v114.3,141.62 106.68,141.62 IC4.10
  Bottom 0.254: v141.6,92.72 157.48,92.72 158.75,91.45 IC24.17 | SV2.16 v38.73,66.06 40.64,66.06 41.91,67.33 43.81,67.33 45.09,68.59 RS08.4 | 48.26,142.25 25.4,142.25 IC1.10 | 48.26,142.25 IC2.10 | 76.2,142.25 48.26,142.25 | 76.2,142.25 IC3.10 | 76.2,142.25 104.14,142.25 IC4.10 | v39.37,93.36 36.2,96.53 v34.29,96.53 | v140.97,140.98 140.34,141.62 v114.3,141.62
DAR09  (via drill 0.61)
  Top 0.254: v29.84,62.24 28.57,63.52 28.57,81.3 29.21,81.93 29.21,83.2 29.84,83.83 29.84,94.63 29.21,95.27 29.21,115.58 26.67,118.12 26.67,138.44 IC1.11 | v132.72,86.38 131.44,87.64 v131.44,101.61 | v114.3,101.61 113.03,102.89 113.03,135.9 107.95,140.98 105.41,140.98 105.41,142.25 104.14,143.52 IC4.11
  Bottom 0.254: 150.5,85.11 150.5,83.2 151.13,82.56 153.67,82.56 154.31,81.93 154.31,80.66 153.67,80.03 143.51,80.03 142.88,80.66 139.06,80.66 138.43,81.3 DAR8-11.6 | 150.5,85.11 157.48,85.11 158.75,86.38 IC24.15 | RS08.5 41.91,66.06 39.37,63.52 SV2.18 34.92,63.52 33.66,62.24 v29.84,62.24 | 46.35,146.7 22.23,146.7 IC1.11 | 46.35,146.7 IC2.11 | 46.35,146.7 74.3,146.7 | 74.3,146.7 IC3.11 | 74.3,146.7 102.23,146.7 IC4.11 | 150.5,85.11 133.99,85.11 v132.72,86.38 | v114.3,101.61 v131.44,101.61
DAR10  (via drill 0.61)
  Top 0.254: v134.62,76.22 134.62,88.92 DAR8-11.2 | v154.94,74.31 157.48,76.85 v157.48,78.75 | v66.04,64.15 65.41,64.78 v65.41,67.33 | v68.58,68.59 v68.58,73.67
  Bottom 0.254: SV2.20 36.2,60.98 36.83,60.34 41.91,60.34 42.55,59.7 43.81,59.7 45.09,60.98 RS08.10 45.72,61.61 48.9,64.78 65.41,64.78 v66.04,64.15 | 135.89,74.95 v134.62,76.22 | 135.89,74.95 146.69,74.95 147.32,74.31 v154.94,74.31 | v157.48,78.75 IC24.13 | v65.41,67.33 66.67,68.59 v68.58,68.59 | v68.58,73.67 79.38,73.67 80.64,72.41 80.64,71.14 109.86,71.14 112.39,73.67 124.46,73.67 126.36,75.58 127.64,75.58 128.27,74.95 135.89,74.95
DAR11  (via drill 0.61)
  Top 0.254: v39.37,58.44 40.01,59.07 v40.01,62.88 | v140.97,88.92 v140.97,78.75 140.97,76.22 v138.43,73.67 | v36.83,99.08 36.83,72.41 32.38,72.41 31.75,71.77 31.75,62.24 33.66,62.24 34.29,61.61 34.29,60.34 35.56,59.07 SV2.22 | v66.04,99.71 67.31,98.44 67.31,91.45 68.58,90.19 v68.58,83.83 | v99.06,83.83 v99.06,90.19 | v127,88.92 v127,74.31
  Bottom 0.254: v40.01,62.88 40.64,63.52 RS08.7 | SV2.22 v39.37,58.44 | v140.97,78.75 142.24,77.48 157.48,77.48 158.75,76.22 IC24.11 | v140.97,88.92 DAR8-11.3 | v36.83,99.08 37.47,99.71 v66.04,99.71 | v68.58,83.83 73.66,83.83 76.2,81.3 78.11,81.3 80.01,83.2 98.42,83.2 v99.06,83.83 | v99.06,90.19 102.23,90.19 102.87,90.82 120.02,90.82 120.65,90.19 125.73,90.19 v127,88.92 | v127,74.31 127.64,73.67 v138.43,73.67
DATA00\
  Bottom 0.254: IC34.12 24.13,20.34 22.86,21.61 9.53,21.61 8.26,22.88 C35L.2
DATA01\
  Bottom 0.254: IC34.14 20.32,25.41 19.05,24.14 9.53,24.14 8.26,25.41 C35L.4
DATA02\
  Bottom 0.254: IC34.16 24.13,30.5 22.86,31.77 13.34,31.77 10.79,29.23 9.53,29.23 8.26,27.96 C35L.6
DATA03\
  Bottom 0.254: IC34.18 20.32,35.58 19.05,34.3 13.34,34.3 10.79,31.77 9.53,31.77 8.26,30.5 C35L.8
DATA04\  (via drill 0.61)
  Top 0.254: v2.54,69.86 1.27,68.59 1.27,20.34 5.08,16.53 8.89,16.53 8.89,31.13 7.62,32.4 C35L.10
  Bottom 0.254: v2.54,69.86 15.24,69.86 16.51,68.59 IC26.3
DATA05\  (via drill 0.61)
  Top 0.254: v12.7,63.52 12.7,40.02 12.06,39.38 v12.06,38.12
  Bottom 0.254: v12.06,38.12 10.79,36.84 9.53,36.84 8.26,35.58 C35L.12 | v12.7,63.52 IC26.5
DATA06\  (via drill 0.61)
  Top 0.254: v14.61,58.44 13.34,57.16 v13.34,39.38
  Bottom 0.254: v13.34,39.38 9.53,39.38 8.26,38.12 C35L.14 | v14.61,58.44 IC26.7
DATA07\  (via drill 0.61)
  Top 0.254: v14.61,41.92 v14.61,52.09
  Bottom 0.254: v14.61,52.09 15.24,52.09 16.51,53.36 IC26.9 | v14.61,41.92 9.53,41.92 8.26,40.66 C35L.16
DATA08\  (via drill 0.61)
  Top 0.254: v24.13,45.73 23.5,46.37 23.5,51.45 IC26.12
  Bottom 0.254: v24.13,45.73 12.06,45.73 10.79,44.47 9.53,44.47 8.26,43.2 C35L.18
DATA09\  (via drill 0.61)
  Top 0.254: v8.89,57.16 8.89,50.18 7.62,48.91 C35L.22
  Bottom 0.254: v8.89,57.16 22.86,57.16 24.13,58.44 IC26.14
DATA10\  (via drill 0.61)
  Top 0.254: v11.43,52.09 v11.43,62.24
  Bottom 0.254: v11.43,62.24 22.86,62.24 24.13,63.52 IC26.16 | v11.43,52.09 9.53,52.09 8.26,50.81 C35L.24
DATA11\  (via drill 0.61)
  Top 0.254: v3.17,53.36 v3.17,67.33
  Bottom 0.254: v3.17,67.33 22.86,67.33 24.13,68.59 IC26.18 | v3.17,53.36 C35L.26
DATA_IN  (via drill 0.61)
  Top 0.254: v80.01,78.12 80.01,94 81.28,95.27 IC22.6 | v123.83,77.48 v123.83,67.96 | v165.74,66.06 167.64,64.15 v167.64,60.98
  Bottom 0.254: v80.01,78.12 113.67,78.12 114.3,78.75 116.2,78.75 117.47,77.48 v123.83,77.48 | v123.83,67.96 151.13,67.96 153.03,66.06 v165.74,66.06 | v167.64,60.98 168.91,59.7 186.06,59.7 187.32,58.44 C36L.30
DCXA\
  Top 0.254: IC18.9 161.93,118.76 160.66,118.76 IC18.10
  Bottom 0.254: IC16.12 106.05,121.3 158.12,121.3 IC18.10
DIMA\  (via drill 0.61)
  Top 0.254: IC37.1 196.22,32.4 196.22,59.07 IC30.1 195.58,63.52 195.58,112.41 v193.68,114.31 | IC17.11 v134.62,114.31
  Bottom 0.254: v134.62,114.31 v193.68,114.31 | IC30.19 204.47,58.44 201.93,60.98 IC30.1
DIML\  (via drill 0.61)
  Top 0.254: v186.69,73.67 186.69,20.34 187.96,19.07 INTENB.11 | v128.27,102.89 130.81,105.42 130.81,116.86 132.08,118.12 IC17.12 | v206.38,90.82 207.65,89.55 207.65,78.12 FIELD.11
  Bottom 0.254: v186.69,73.67 190.5,77.48 200.66,77.48 201.93,76.22 FIELD.11 | v128.27,102.89 171.45,102.89 173.35,100.98 196.22,100.98 196.85,100.34 199.39,100.34 206.38,93.36 v206.38,90.82
DIO00  (via drill 0.61)
  Top 0.254: v44.45,122.57 45.72,121.3 IC14.12 | v50.16,27.96 v50.16,19.07 49.53,18.43 v49.53,8.91 | v15.88,16.53 15.88,20.97 | 15.88,20.97 IC34.8 | 15.88,20.97 15.88,74.31 16.51,74.95 16.51,116.86 17.78,118.12 IC13.12
  Bottom 0.254: v44.45,122.57 20.95,122.57 IC13.12 | v50.16,19.07 58.42,19.07 59.69,20.34 IC35.12 | v50.16,27.96 RS08.36 | v15.88,16.53 22.23,10.18 SV1.2 33.66,10.18 34.92,8.91 v49.53,8.91
DIO01  (via drill 0.61)
  Top 0.254: v31.11,26.69 31.11,15.26 33.02,13.35 SV1.4 | v12.06,116.86 8.89,113.68 8.89,95.27 10.16,94 10.16,73.04 11.43,71.77 v11.43,64.78 | v6.35,26.69 v6.35,54.62
  Bottom 0.254: IC14.11 46.35,121.3 22.23,121.3 IC13.11 17.78,116.86 v12.06,116.86 | 45.09,26.69 54.61,26.69 55.24,26.05 59.05,26.05 59.69,25.41 IC35.14 | 45.09,26.69 43.81,25.41 RS08.37 | 20.32,26.69 19.05,27.96 IC34.6 | 45.09,26.69 v31.11,26.69 20.32,26.69 | v11.43,64.78 9.53,64.78 8.89,64.15 8.89,59.7 6.99,59.7 6.35,59.07 v6.35,54.62 | v6.35,26.69 20.32,26.69
DIO02  (via drill 0.61)
  Top 0.254: v20.95,33.04 21.59,32.4 v21.59,15.26 | v59.05,21.61 59.05,28.59 IC35.16 | v39.37,116.86 39.37,94.63 38.1,93.36 v38.1,91.45 | v66.67,90.82 66.04,90.19 66.04,69.23 66.67,68.59 66.67,64.78 67.31,64.15 v67.31,33.04
  Bottom 0.254: IC13.10 25.4,116.86 v39.37,116.86 49.53,116.86 50.8,118.12 IC14.10 | RS08.35 43.81,27.96 45.09,29.23 54.61,29.23 55.88,30.5 IC35.16 64.77,30.5 v67.31,33.04 | v20.95,33.04 IC34.4 | v21.59,15.26 SV1.6 33.66,15.26 34.92,16.53 36.2,16.53 37.47,17.8 39.37,17.8 40.64,16.53 57.15,16.53 59.69,19.07 62.87,19.07 62.87,20.97 62.23,21.61 v59.05,21.61 | v38.1,91.45 61.59,91.45 62.87,90.19 66.04,90.19 v66.67,90.82
DIO03  (via drill 0.61)
  Top 0.254: IC34.2 19.68,36.21 v19.68,29.23 19.68,17.16 v20.32,16.53 | v59.05,31.77 59.05,33.67 IC35.18 | v2.54,108.6 2.54,71.14 3.81,69.86 3.81,69.23 1.91,67.33 1.91,39.38 v3.81,37.48 | v25.4,115.58 IC13.9
  Bottom 0.254: IC13.9 27.3,117.49 35.56,117.49 37.47,119.39 38.73,119.39 39.37,118.76 39.37,118.12 40.01,117.49 48.9,117.49 49.53,118.12 49.53,121.3 51.44,121.3 IC14.9 | v19.68,29.23 36.2,29.23 37.47,30.5 RS08.33 43.81,30.5 45.09,31.77 v59.05,31.77 | v20.32,16.53 31.11,16.53 32.38,17.8 SV1.8 | v25.4,115.58 9.53,115.58 v2.54,108.6 | v3.81,37.48 6.99,34.3 12.06,34.3 15.88,38.12 IC34.2
DIO04  (via drill 0.61)
  Top 0.254: 36.83,21.61 34.92,21.61 33.66,20.34 SV1.10 | 36.83,21.61 v36.83,47.01 | v27.3,82.56 27.3,67.96 IC26.17 | v56.52,82.56 56.52,71.77 IC28.3 | IC15.2 71.12,106.7 69.85,105.42 v69.85,82.56 69.85,67.33 71.75,67.33 72.39,66.69 72.39,36.84 v69.85,36.84 | 36.83,21.61 36.83,15.26 v38.1,13.99 | v48.26,12.71 48.9,13.35 48.9,31.13 52.07,34.3 54.61,34.3 55.88,33.04 56.52,33.04 56.52,33.67 57.15,34.3 57.15,34.94 v56.52,35.58
  Bottom 0.254: v36.83,47.01 43.81,47.01 44.45,46.37 44.45,45.1 45.72,43.83 RS08.24 | v27.3,82.56 v56.52,82.56 57.15,83.2 57.78,83.2 58.42,82.56 v69.85,82.56 | v38.1,13.99 45.09,13.99 46.35,12.71 v48.26,12.71 | v56.52,35.58 57.78,36.84 v69.85,36.84
DIO05  (via drill 0.61)
  Top 0.254: v30.48,41.92 30.48,54.62 27.3,57.8 27.3,59.07 IC26.15 22.86,58.44 22.86,42.56 23.5,41.92 23.5,37.48 24.13,36.84 23.5,36.21 v23.5,24.14 | 57.15,59.7 57.15,42.56 v57.78,41.92 | 57.15,59.7 IC28.5 | v59.05,110.5 59.05,106.06 59.69,105.42 59.69,81.3 57.15,78.75 57.15,59.7
  Bottom 0.254: v30.48,41.92 43.81,41.92 45.09,40.66 RS08.26 48.9,40.66 50.16,41.92 v57.78,41.92 | v59.05,110.5 67.31,110.5 IC15.1 | v23.5,24.14 31.11,24.14 32.38,22.88 SV1.12
DIO06  (via drill 0.61)
  Top 0.254: v26.67,43.83 27.3,44.47 27.3,53.99 IC26.13 | v40.01,44.47 40.64,43.83 v40.64,36.84 40.64,25.41 v39.37,24.14 | v56.52,37.48 56.52,55.26 IC28.7 | v65.41,106.7 65.41,108.6 67.31,110.5 67.31,114.31 71.12,118.12 IC15.13 | v50.8,106.7 49.53,105.42 49.53,89.55 47.62,87.64 47.62,76.85 49.53,74.95 49.53,61.61 v48.9,60.98
  Bottom 0.254: v26.67,43.83 39.37,43.83 v40.01,44.47 | v40.64,36.84 43.81,36.84 | 43.81,36.84 45.09,38.12 RS08.28 | v56.52,37.48 55.88,36.84 43.81,36.84 | v50.8,106.7 v65.41,106.7 | v48.9,60.98 51.44,58.44 IC28.7 | v39.37,24.14 34.92,24.14 33.66,25.41 SV1.14
DIO07  (via drill 0.61)
  Top 0.254: v69.85,106.7 69.85,114.31 73.66,118.12 IC15.12 | v53.34,100.98 52.7,100.34 52.7,98.44 52.07,97.81 52.07,80.03 49.53,77.48 49.53,76.22 50.16,75.58 50.16,54.62 v49.53,53.99 | v33.02,51.45 33.02,45.1 31.75,43.83 31.75,29.86 33.02,28.59 SV1.16 | v50.8,35.58 51.44,36.21 51.44,38.75 52.07,39.38 55.88,39.38 55.88,50.81 IC28.9
  Bottom 0.254: 33.02,52.09 35.56,52.09 36.83,50.81 41.27,50.81 42.55,52.09 48.9,52.09 50.16,53.36 | 33.02,52.09 27.94,52.09 26.67,50.81 IC26.11 | 50.16,53.36 IC28.9 | v69.85,106.7 69.85,102.25 67.31,102.25 66.67,101.61 59.69,101.61 59.05,102.25 54.61,102.25 v53.34,100.98 | 50.16,53.36 v49.53,53.99 | v33.02,51.45 33.02,52.09 | v50.8,35.58 RS08.30
DIO08  (via drill 0.61)
  Top 0.254: v29.21,31.77 v29.21,54.62 | v49.53,33.04 49.53,51.45 v50.16,52.09 50.8,52.72 v50.8,77.48 | v61.59,78.75 61.59,121.3 74.3,121.3 IC15.11
  Bottom 0.254: v29.21,54.62 20.32,54.62 19.05,55.9 IC26.8 | v29.21,31.77 30.48,30.5 SV1.18 33.66,30.5 34.92,31.77 43.81,31.77 45.09,33.04 RS08.32 v49.53,33.04 | v50.16,52.09 58.42,52.09 59.69,53.36 IC28.12 | v61.59,78.75 60.33,77.48 v50.8,77.48
DIO09  (via drill 0.61)
  Top 0.254: v77.47,126.38 77.47,121.94 78.74,120.67 IC15.10 | v12.7,91.45 13.97,90.19 13.97,66.06 12.7,64.78 14.61,62.88 v14.61,60.98 | v30.48,33.04 v30.48,38.12 | v27.94,38.12 v27.94,55.9
  Bottom 0.254: RS08.29 42.55,35.58 41.27,34.3 34.92,34.3 33.66,33.04 SV1.20 v30.48,33.04 | 29.21,57.16 58.42,57.16 59.69,58.44 IC28.14 | 29.21,57.16 26.67,59.7 20.32,59.7 19.05,60.98 IC26.6 v14.61,60.98 | v77.47,126.38 76.83,127.02 7.62,127.02 1.27,120.67 1.27,91.45 v12.7,91.45 | v30.48,38.12 v27.94,38.12 | v27.94,55.9 29.21,57.16
DIO10  (via drill 0.61)
  Top 0.254: v12.7,80.66 v12.7,66.06 | v25.4,92.09 26.67,93.36 v26.67,107.97 | v78.74,109.23 80.01,110.5 80.01,116.86 81.28,118.12 IC15.9 | v64.77,63.52 64.14,64.15 v64.14,109.23 | v48.26,39.38 47.62,40.02 47.62,61.61 v48.26,62.24
  Bottom 0.254: SV1.22 33.66,35.58 34.92,36.84 39.37,36.84 40.64,38.12 RS08.27 43.81,38.12 45.09,39.38 v48.26,39.38 | v12.7,80.66 24.13,92.09 v25.4,92.09 | v26.67,107.97 27.94,109.23 v64.14,109.23 v78.74,109.23 | v12.7,66.06 IC26.4 | v64.77,63.52 IC28.16 55.88,63.52 54.61,62.24 v48.26,62.24
DIO11  (via drill 0.61)
  Top 0.254: v85.09,93.36 85.72,94 85.72,116.22 83.82,118.12 IC15.8 | v66.04,93.36 65.41,92.72 v65.41,68.59 | v21.59,39.38 21.59,62.88 20.95,63.52 20.95,69.23 v21.59,69.86
  Bottom 0.254: RS08.25 42.55,40.66 41.27,39.38 34.92,39.38 33.66,38.12 SV1.24 32.38,38.12 31.11,39.38 v21.59,39.38 | IC26.2 19.05,71.14 20.32,69.86 v21.59,69.86 58.42,69.86 59.69,68.59 IC28.18 v65.41,68.59 | v66.04,93.36 v85.09,93.36
DIOEVEN  (via drill 0.61)
  Top 0.254: v50.16,30.5 50.16,29.23 54.61,29.23 55.24,28.59 55.24,22.24 IC35.9 | v11.43,86.38 11.43,114.31 15.24,118.12 IC13.13
  Bottom 0.254: v50.16,30.5 RS08.34 | v11.43,86.38 1.27,76.22 1.27,19.07 48.9,19.07 50.16,20.34 IC35.9
DMA00  (via drill 0.61)
  Top 0.254: v150.5,5.73 150.5,10.81 IC38.8 | v28.57,83.83 28.57,82.56 27.94,81.93 27.94,59.07 v31.11,55.9 | v109.22,38.12 110.49,36.84 110.49,7 114.3,7 117.47,10.18 DMA0-3.7 | v78.11,76.22 v78.11,50.81 | v62.87,91.45 v62.87,78.75 | v34.29,92.72 33.02,91.45 SV2.1
  Bottom 0.254: v150.5,5.73 127.64,5.73 123.19,10.18 DMA0-3.7 | 37.47,54.62 36.2,55.9 SV2.24 | 37.47,54.62 43.81,54.62 45.09,53.36 RS08.16 | v31.11,55.9 32.38,54.62 37.47,54.62 | v28.57,83.83 SV2.1 | v109.22,38.12 101.6,45.73 83.19,45.73 v78.11,50.81 | v78.11,76.22 75.56,78.75 v62.87,78.75 | v62.87,91.45 62.23,92.09 38.73,92.09 38.1,92.72 v34.29,92.72
DMA01  (via drill 0.61)
  Top 0.254: v134.62,17.8 134.62,6.36 128.27,6.36 DMA0-3.6 | v76.2,47.01 77.47,45.73 77.47,13.35 v78.74,12.08 | v67.31,83.83 67.31,66.69 69.22,64.78 69.22,60.34 68.58,59.7 68.58,48.91 v69.22,48.27
  Bottom 0.254: v134.62,17.8 135.89,16.53 149.86,16.53 151.13,17.8 IC38.6 | v76.2,47.01 70.48,47.01 v69.22,48.27 59.05,48.27 58.42,47.64 46.99,47.64 46.35,48.27 RS08.20 | v78.74,12.08 80.01,10.81 118.75,10.81 120.65,12.71 DMA0-3.6 | v67.31,83.83 56.52,83.83 55.88,83.2 45.72,83.2 43.81,85.11 26.04,85.11 26.04,82.56 27.3,81.3 SV2.3
DMA02  (via drill 0.61)
  Top 0.254: v44.45,78.75 44.45,57.8 45.72,56.53 RS08.14 | v102.87,20.97 102.87,40.66 104.14,41.92 104.14,62.88 105.41,64.15 105.41,86.38 102.87,88.92 v102.87,89.55 | v50.8,89.55 48.9,87.64 v48.9,80.66
  Bottom 0.254: IC38.4 151.13,22.88 149.86,21.61 124.46,21.61 123.19,22.88 DMA0-3.2 120.65,22.88 118.75,20.97 v102.87,20.97 | v44.45,78.75 43.18,80.03 | 43.18,80.03 34.92,80.03 33.66,78.75 SV2.5 | v102.87,89.55 102.23,88.92 78.11,88.92 76.2,90.82 74.93,90.82 73.03,88.92 51.44,88.92 v50.8,89.55 | v48.9,80.66 48.26,80.03 43.18,80.03
DMA03  (via drill 0.61)
  Top 0.254: v48.26,73.67 47.62,73.04 47.62,62.88 46.99,62.24 46.99,60.34 45.72,59.07 RS08.12 45.72,57.8 46.99,56.53 46.99,14.62 47.62,13.99 47.62,13.35 46.99,12.71 v46.99,6.36 | v124.46,30.5 124.46,22.88 DMA0-3.3 | v64.14,6.36 67.31,3.19 85.72,3.19 v85.72,14.62 | v114.3,16.53 118.11,20.34 v118.11,29.23
  Bottom 0.254: v48.26,73.67 46.99,74.95 34.92,74.95 33.66,76.22 SV2.7 | IC38.2 151.13,27.96 149.86,29.23 125.73,29.23 v124.46,30.5 119.38,30.5 v118.11,29.23 | v46.99,6.36 v64.14,6.36 | v85.72,14.62 88.27,17.16 113.67,17.16 v114.3,16.53
DMA04  (via drill 0.61)
  Top 0.254: v31.11,60.98 31.11,72.41 32.38,73.67 SV2.9 | v123.83,40.66 123.83,42.56 DMA4-7.7 | v138.43,40.02 142.88,44.47 v142.88,45.73 | v104.14,88.92 106.05,87.01 106.05,53.36 v105.41,52.72
  Bottom 0.254: v31.11,60.98 32.38,59.7 33.66,59.7 34.29,60.34 34.29,61.61 34.92,62.24 39.37,62.24 40.64,60.98 RS08.9 | v123.83,40.66 124.46,40.02 v138.43,40.02 | v142.88,45.73 149.86,45.73 151.13,47.01 IC31.8 | v104.14,88.92 103.5,88.28 74.93,88.28 74.3,87.64 44.45,87.64 43.18,88.92 38.73,88.92 37.47,87.64 22.86,87.64 22.86,83.2 32.38,73.67 SV2.9 | v105.41,52.72 106.05,52.09 115.57,52.09 120.02,47.64 120.02,45.1 121.28,45.1 DMA4-7.7
DMA05  (via drill 0.61)
  Top 0.254: v36.83,67.33 36.83,69.86 34.92,69.86 33.66,71.14 SV2.11 | v40.01,67.33 40.64,66.69 40.64,63.52 41.91,62.24 41.91,60.34 43.18,59.07 RS08.11 | v125.73,52.09 125.73,50.81 DMA4-7.6 | v21.59,74.95 v21.59,72.41 | v3.81,74.95 4.45,74.31 4.45,57.16 3.81,56.53 3.81,53.99 4.45,53.36 4.45,52.09 3.81,51.45 3.81,38.75 5.08,37.48 v5.08,17.8 | v67.31,5.73 69.22,3.83 74.93,3.83 v74.93,11.45 | v91.44,15.89 92.71,17.16 v92.71,52.72
  Bottom 0.254: v36.83,67.33 v40.01,67.33 | 127,53.36 v125.73,52.09 | 127,53.36 149.86,53.36 151.13,52.09 IC31.6 | v21.59,72.41 26.67,72.41 27.3,71.77 31.75,71.77 32.38,71.14 SV2.11 | v3.81,74.95 v21.59,74.95 | v5.08,17.8 15.88,7 44.45,7 46.35,5.09 66.67,5.09 v67.31,5.73 | v74.93,11.45 76.83,13.35 88.9,13.35 v91.44,15.89 | v92.71,52.72 93.98,53.99 110.49,53.99 111.12,54.62 119.38,54.62 120.65,53.36 127,53.36
DMA06  (via drill 0.61)
  Top 0.254: v40.01,55.9 38.1,57.8 v38.1,64.78 | v29.84,68.59 30.48,69.23 30.48,85.74 v31.11,86.38 | v118.11,85.11 118.75,84.47 118.75,66.69 118.11,66.06 v118.11,56.53
  Bottom 0.254: v38.1,64.78 34.92,64.78 34.29,65.42 34.29,67.96 33.02,67.96 SV2.13 v29.84,68.59 | v40.01,55.9 RS08.13 | IC31.4 149.22,57.16 147.96,55.9 124.46,55.9 123.19,57.16 DMA4-7.2 118.75,57.16 v118.11,56.53 | v31.11,86.38 31.75,85.74 79.38,85.74 80.01,86.38 116.84,86.38 v118.11,85.11
DMA07  (via drill 0.61)
  Top 0.254: v40.01,53.36 37.47,55.9 37.47,63.52 36.2,64.78 | 36.2,64.78 33.02,64.78 SV2.15 | v149.22,64.78 v149.22,62.24 | DMA4-7.3 125.09,57.8 v125.09,62.88 126.36,64.15 126.36,73.04 125.73,73.67 125.73,83.83 v124.46,85.11 | 36.2,64.78 38.1,66.69 v38.1,87.01
  Bottom 0.254: v40.01,53.36 RS08.15 | v125.09,62.88 127,64.78 v149.22,64.78 | v149.22,62.24 IC31.2 | v38.1,87.01 38.73,86.38 78.74,86.38 79.38,87.01 118.75,87.01 120.65,85.11 v124.46,85.11
DMA08  (via drill 0.61)
  Top 0.254: v41.27,52.09 42.55,50.81 RS08.17 | v38.73,52.09 36.83,53.99 36.83,61.61 36.2,62.24 34.92,62.24 33.66,63.52 SV2.17 | v123.83,82.56 123.83,80.66 DMA8-11.7 | v23.5,64.78 22.86,65.42 22.86,80.66 28.57,86.38 v28.57,88.92 | v83.82,91.45 85.09,90.19 v85.09,84.47
  Bottom 0.254: v38.73,52.09 v41.27,52.09 | IC24.8 148.59,81.3 147.32,82.56 v123.83,82.56 118.11,82.56 115.57,85.11 85.72,85.11 v85.09,84.47 | v23.5,64.78 31.11,64.78 32.38,63.52 SV2.17 | v28.57,88.92 29.84,90.19 50.16,90.19 50.8,90.82 60.96,90.82 62.23,89.55 72.39,89.55 74.3,91.45 v83.82,91.45
DMA09  (via drill 0.61)
  Top 0.254: v114.3,77.48 114.3,80.03 v115.57,81.3 115.57,128.28 v114.94,128.92 | v81.28,76.85 79.38,74.95 v79.38,72.41 | v59.05,72.41 58.42,71.77 58.42,47.64 v59.05,47.01 | v149.22,87.01 148.59,87.64 v148.59,101.61 | v135.89,101.61 136.53,102.25 136.53,108.6 138.43,110.5 v138.43,128.28 | v34.29,50.81 34.29,59.07 33.02,60.34 SV2.19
